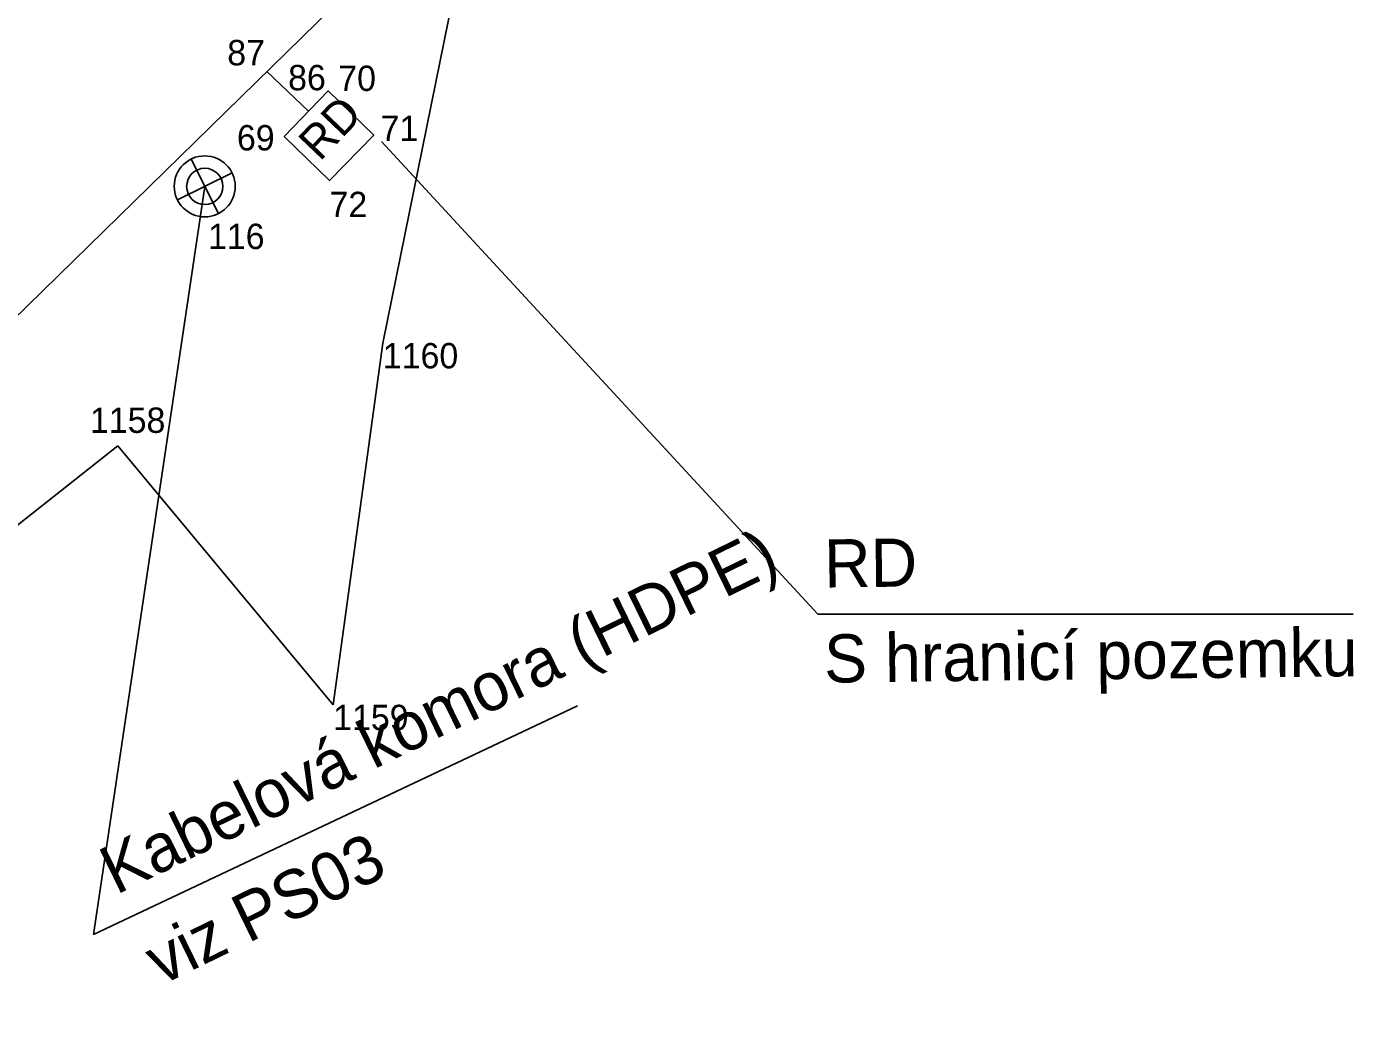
# Model space of a CAD drawing. Extents: x -678683 to -677755, y -1006946 to -1005971.
# Drawn here: x -678303 to -678250.7, y -1006558 to -1006518.8 of the extents above; entities that cross this region are included whole.
import ezdxf

# ---------------------------------------------------------------- set-up
doc = ezdxf.new("R2010")
doc.units = 0
for name, color, linetype in [('Schéma kabelů', 7, 'Continuous'), ('SSZT nové - lomové body', 7, 'Continuous'), ('SSZT_nové', 7, 'Continuous'), ('SŽDC', 7, 'Continuous'), ('SŽDC - body', 7, 'Continuous')]:
    doc.layers.add(name, color=color, linetype=linetype)

msp = doc.modelspace()

# ---------------------------------------------------------------- linework, layer by layer
at = {"layer": 'Schéma kabelů'}
for p, q in [((-678296.523, -1006524.026), (-678295.448, -1006526.178)), ((-678297.062, -1006525.639), (-678294.91, -1006524.564))]:
    msp.add_line(p, q, dxfattribs=at)
for radius in [1.203, 0.714]:
    msp.add_circle((-678295.986, -1006525.102), radius, dxfattribs=at)
at = {"layer": 'SSZT nové - lomové body'}
for p, q in [((-678293.53, -1006520.566), (-678293.53, -1006520.566)), ((-678291.113, -1006521.338), (-678291.113, -1006521.338)), ((-678291.888, -1006522.135), (-678291.888, -1006522.135)), ((-678292.854, -1006523.132), (-678292.854, -1006523.132)), ((-678289.318, -1006523.079), (-678289.318, -1006523.079)), ((-678291.059, -1006524.873), (-678291.059, -1006524.873))]:
    msp.add_line(p, q, dxfattribs=at)
at = {"layer": 'SSZT_nové'}
for p, q in [((-678291.888, -1006522.135), (-678293.53, -1006520.566)), ((-678289.017, -1006523.33), (-678271.798, -1006541.973)), ((-678295.986, -1006525.102), (-678300.373, -1006554.614)), ((-678250.688, -1006541.973), (-678271.798, -1006541.973)), ((-678281.286, -1006545.596), (-678300.373, -1006554.614))]:
    msp.add_line(p, q, dxfattribs=at)
msp.add_lwpolyline([(-678506.624, -1006791.938), (-678466.12, -1006753.227), (-678449.329, -1006728.75), (-678428.753, -1006695.612), (-678421.07, -1006681.971), (-678401.666, -1006635.236), (-678393.87, -1006623.108), (-678390.132, -1006617.261), (-678380.001, -1006603.755), (-678359.836, -1006584.701), (-678339.66, -1006565.68), (-678276.518, -1006503.932), (-678276.518, -1006503.932)], dxfattribs=at)
msp.add_lwpolyline([(-678292.854, -1006523.132), (-678291.113, -1006521.338), (-678289.318, -1006523.079), (-678291.059, -1006524.873)], close=True, dxfattribs=at)
at = {"layer": 'SŽDC'}
for p, q in [((-678288.96, -1006531.28), (-678285.543, -1006514.493)), ((-678290.92, -1006545.55), (-678288.96, -1006531.28)), ((-678316.02, -1006548.44), (-678299.42, -1006535.34)), ((-678299.42, -1006535.34), (-678290.92, -1006545.55))]:
    msp.add_line(p, q, dxfattribs=at)
at = {"layer": 'SŽDC - body'}
for p, q in [((-678288.96, -1006531.28), (-678288.96, -1006531.28)), ((-678299.42, -1006535.34), (-678299.42, -1006535.34)), ((-678290.92, -1006545.55), (-678290.92, -1006545.55))]:
    msp.add_line(p, q, dxfattribs=at)

# ---------------------------------------------------------------- texts
at = {"layer": 'SSZT nové - lomové body'}
for s, p in [('87', (-678295.098, -1006520.327)), ('86', (-678292.697, -1006521.312)), ('70', (-678290.719, -1006521.339)), ('71', (-678289.052, -1006523.316)), ('69', (-678294.716, -1006523.684)), ('72', (-678291.064, -1006526.316)), ('116', (-678295.858, -1006527.574))]:
    msp.add_text(s, height=1, dxfattribs=at).set_placement(p)
at = {"layer": 'SSZT_nové'}
for s, height, rotation, p in [('RD', 1.306, 46.3725, (-678291.446, -1006524.144)), ('Kabelová komora (HDPE)', 1.9, 25.9995, (-678299.483, -1006553.061)), ('RD', 1.9, 0.7098, (-678271.542, -1006540.928)), ('S hranicí pozemku', 1.9, 0.7098, (-678271.542, -1006544.68)), ('viz PS03', 1.9, 25.9995, (-678297.71, -1006556.634))]:
    msp.add_text(s, height=height, rotation=rotation, dxfattribs=at).set_placement(p)
at = {"layer": 'SŽDC - body'}
for s, p in [('1160', (-678288.96, -1006532.28)), ('1158', (-678300.514, -1006534.825)), ('1159', (-678290.92, -1006546.55))]:
    msp.add_text(s, height=1, dxfattribs=at).set_placement(p)

doc.saveas('drawing.dxf')
